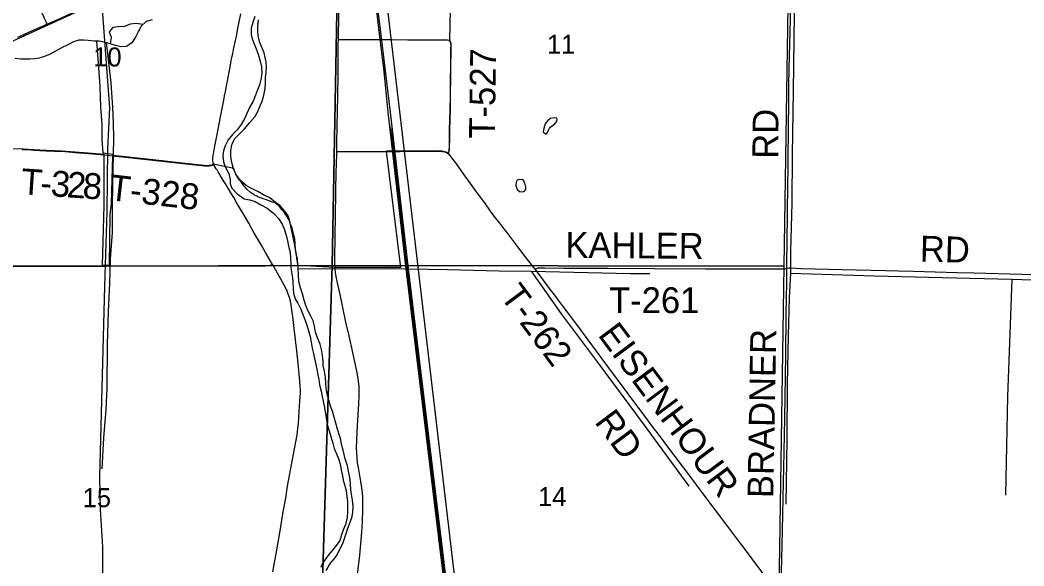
# Model space of a CAD drawing. Extents: x -8.3 to 42.1, y 0 to 22.
# Drawn here: x 5.164 to 7.372, y 15.682 to 16.882 of the extents above; entities that cross this region are included whole.
import ezdxf

# ---------------------------------------------------------------- set-up
doc = ezdxf.new("R2010")
doc.units = 0
for name, color, linetype in [('GM_X_City_Street', 7, 'Continuous'), ('GM_X_Corporation', 7, 'Continuous'), ('GM_X_County_Road', 7, 'Continuous'), ('GM_X_Major_River', 7, 'Continuous'), ('GM_X_Minor_Lake', 7, 'Continuous'), ('GM_X_Minor_River', 7, 'Continuous'), ('GM_X_Rail_Line', 7, 'Continuous'), ('GM_X_Section', 7, 'Continuous'), ('GM_X_Section_Text', 7, 'Continuous'), ('GM_X_State_Route', 7, 'Continuous'), ('GM_X_Township_Road', 7, 'Continuous'), ('GM_X_Township_Road_Text', 7, 'Continuous')]:
    doc.layers.add(name, color=color, linetype=linetype)

msp = doc.modelspace()

# ---------------------------------------------------------------- linework, layer by layer
at = {"layer": 'GM_X_City_Street'}
for points in [[(5.2228, 16.873), (5.2206, 16.8781), (5.2187, 16.8825), (5.2174, 16.8853), (5.2155, 16.8895), (5.2128, 16.8951), (5.2102, 16.9009)], [(5.8638, 16.8392), (5.8673, 16.8392), (5.8799, 16.8392), (5.8923, 16.839), (5.9124, 16.8392), (5.9202, 16.8391), (5.9341, 16.8391), (5.945, 16.8391), (5.9574, 16.839), (5.9822, 16.8388), (6.0163, 16.8387), (6.0349, 16.8387), (6.0535, 16.8386), (6.0815, 16.8386), (6.097, 16.8385), (6.1017, 16.8382), (6.1041, 16.8381), (6.1066, 16.8376), (6.1084, 16.8364)]]:
    msp.add_lwpolyline(points, dxfattribs=at)
at = {"layer": 'GM_X_Corporation'}
msp.add_lwpolyline([(6.1166, 17.2491), (6.1082, 16.8369), (6.1097, 16.8351), (6.1107, 16.8333), (6.1112, 16.8306), (6.1113, 16.8268), (6.111, 16.8225), (6.1109, 16.8163), (6.1108, 16.8102), (6.1109, 16.8024), (6.1106, 16.79), (6.1107, 16.7806), (6.1106, 16.776), (6.1106, 16.7698), (6.1106, 16.7667), (6.1105, 16.7652), (6.1103, 16.759), (6.11, 16.7497), (6.1101, 16.7451), (6.11, 16.7435), (6.1098, 16.7311), (6.1098, 16.7156), (6.1094, 16.6845), (6.1083, 16.6411), (6.1079, 16.6209), (6.1075, 16.6023), (6.1073, 16.5967), (6.1069, 16.5939), (6.1055, 16.5883), (6.1031, 16.5901), (6.1006, 16.5914), (6.0973, 16.5925), (6.0918, 16.5933), (6.084, 16.5938), (6.07, 16.5941), (6.0263, 16.5939), (5.9997, 16.5937), (5.9841, 16.5936), (5.9691, 16.5936), (6.0001, 16.3379), (5.856, 16.3381), (5.7751, 16.3419), (5.7739, 16.3491), (5.7736, 16.3535), (5.7736, 16.3573), (5.7729, 16.3598), (5.7724, 16.3626), (5.7712, 16.3671), (5.7701, 16.3728), (5.7701, 16.3749), (5.7692, 16.3778), (5.7679, 16.4016), (5.7675, 16.4046), (5.7653, 16.411), (5.7644, 16.4158), (5.7625, 16.4214), (5.7611, 16.4267), (5.7589, 16.4319), (5.7576, 16.4346), (5.7573, 16.4357), (5.7566, 16.4381), (5.7538, 16.4446), (5.7534, 16.4459), (5.752, 16.448), (5.7514, 16.4492), (5.7502, 16.4506), (5.7481, 16.4535), (5.7461, 16.4563), (5.7446, 16.4594), (5.7427, 16.462), (5.7394, 16.4649), (5.7378, 16.4667), (5.7371, 16.468), (5.734, 16.4722), (5.7315, 16.475), (5.7308, 16.4756), (5.7278, 16.4772), (5.7273, 16.4776), (5.7267, 16.4781), (5.7245, 16.4797), (5.7236, 16.4802), (5.7228, 16.4805), (5.7216, 16.481), (5.7191, 16.4817), (5.7166, 16.4823), (5.7114, 16.4842), (5.7093, 16.4851), (5.7032, 16.4873), (5.6986, 16.4887), (5.6944, 16.4906), (5.6899, 16.4918), (5.6864, 16.493), (5.6846, 16.4943), (5.6794, 16.4971), (5.6777, 16.4985), (5.6757, 16.4995), (5.6725, 16.5013), (5.6704, 16.5028), (5.6628, 16.509), (5.6542, 16.5193), (5.6514, 16.5237), (5.6491, 16.5273), (5.6485, 16.5278), (5.6476, 16.5286), (5.6465, 16.53), (5.6443, 16.5324), (5.6425, 16.5345), (5.641, 16.5369), (5.6406, 16.5378), (5.6398, 16.5397), (5.6385, 16.5425), (5.6374, 16.545), (5.6372, 16.5457), (5.637, 16.5464), (5.6365, 16.5477), (5.6355, 16.5494), (5.6352, 16.55), (5.6347, 16.5527), (5.6343, 16.5537), (5.634, 16.5544), (5.634, 16.5548), (5.6338, 16.5555), (5.5894, 16.565), (5.5867, 16.5636), (5.5836, 16.5624), (5.5795, 16.5618), (5.5764, 16.5615), (5.5733, 16.5616), (5.5687, 16.5619), (5.5146, 16.568), (5.4621, 16.5739), (5.4019, 16.5803), (5.367, 16.5841), (5.3636, 16.4788), (5.3613, 16.4541), (5.3595, 16.342), (5.3451, 16.3421), (5.3486, 16.4746), (5.3482, 16.4891), (5.3489, 16.586), (5.3401, 16.5869), (5.3137, 16.589), (5.2843, 16.5916), (5.2549, 16.5939), (5.2394, 16.5945), (5.2208, 16.595), (5.2068, 16.5956), (5.1929, 16.5966), (5.1805, 16.5976), (5.1711, 16.5978), (5.168, 16.5978), (5.1062, 16.5996)], dxfattribs=at)
at = {"layer": 'GM_X_County_Road'}
for points in [[(5.5896, 16.5645), (5.5884, 16.5683), (5.5876, 16.5725), (5.5874, 16.5758), (5.5874, 16.5788), (5.588, 16.5834), (5.5897, 16.5925), (5.592, 16.6047), (5.5957, 16.623), (5.6001, 16.6459), (5.6038, 16.6657), (5.6109, 16.7022), (5.6143, 16.7189), (5.6159, 16.7281), (5.6171, 16.7341), (5.6182, 16.7402), (5.6191, 16.7447), (5.6197, 16.7478), (5.6212, 16.7553), (5.6236, 16.7674), (5.6249, 16.775), (5.6263, 16.7825), (5.6282, 16.7931), (5.6294, 16.7992), (5.6313, 16.8083), (5.6331, 16.8174), (5.6375, 16.8371), (5.6394, 16.8461), (5.642, 16.8596), (5.6434, 16.8671), (5.6449, 16.8745), (5.6492, 16.8958)], [(5.8638, 16.8392), (5.8649, 16.8943), (5.8651, 16.9135)], [(5.8602, 16.593), (5.8606, 16.613), (5.8613, 16.6456), (5.862, 16.6829), (5.8625, 16.714), (5.8629, 16.7653), (5.8632, 16.7886), (5.8636, 16.8073), (5.8636, 16.8321), (5.8638, 16.8392)], [(5.8563, 16.3375), (5.8562, 16.3432), (5.856, 16.3534), (5.8566, 16.4109), (5.8572, 16.4482), (5.8581, 16.5057), (5.8591, 16.5492), (5.8594, 16.5632), (5.8602, 16.5897), (5.8602, 16.593)], [(5.7186, 16.3446), (5.7036, 16.3705), (5.695, 16.3853), (5.678, 16.4149), (5.6734, 16.423), (5.6665, 16.4351), (5.654, 16.4565), (5.6405, 16.4793), (5.6336, 16.4914), (5.6273, 16.5021), (5.6169, 16.5194), (5.6111, 16.5286), (5.6047, 16.5392), (5.6016, 16.5445), (5.5993, 16.5485), (5.5968, 16.5524), (5.5951, 16.555), (5.5928, 16.5585), (5.5908, 16.5618), (5.5896, 16.5645)], [(5.7198, 15.6684), (5.7276, 15.7128), (5.7305, 15.7297), (5.7347, 15.7542), (5.7425, 15.8002), (5.7478, 15.8308), (5.7521, 15.8569), (5.7585, 15.8921), (5.7653, 15.9272), (5.7705, 15.9547), (5.7731, 15.97), (5.7749, 15.9839), (5.776, 15.9948), (5.7777, 16.0212), (5.7791, 16.0444), (5.7801, 16.0615), (5.7802, 16.0694), (5.78, 16.0772), (5.7791, 16.0881), (5.7751, 16.1267), (5.7721, 16.1546), (5.7663, 16.204), (5.7634, 16.2302), (5.7617, 16.2441), (5.7598, 16.2565), (5.7583, 16.2641), (5.7562, 16.2717), (5.7535, 16.2791), (5.75, 16.2877), (5.7453, 16.2976), (5.7402, 16.3073), (5.7192, 16.3436), (5.7186, 16.3446)], [(5.9051, 15.6572), (5.9106, 15.705), (5.9141, 15.739), (5.9154, 15.756), (5.9167, 15.7792), (5.9176, 15.8056), (5.9177, 15.8196), (5.9175, 15.832), (5.9168, 15.8428), (5.9156, 15.8535), (5.9133, 15.8673), (5.9085, 15.8933), (5.9061, 15.9086), (5.9048, 15.9195), (5.9041, 15.9304), (5.9039, 15.9413), (5.9041, 15.9568), (5.905, 15.977), (5.9074, 16.0143), (5.9086, 16.0375), (5.9093, 16.0561), (5.9094, 16.0685), (5.9091, 16.0778), (5.9083, 16.0855), (5.907, 16.0946), (5.9042, 16.1099), (5.9007, 16.1266), (5.8953, 16.1509), (5.8871, 16.1872), (5.8803, 16.2176), (5.8735, 16.2495), (5.8673, 16.2783), (5.8618, 16.3041), (5.8589, 16.3178), (5.8573, 16.3271), (5.8564, 16.3348), (5.8563, 16.3375)]]:
    msp.add_lwpolyline(points, dxfattribs=at)
at = {"layer": 'GM_X_Major_River'}
for points in [[(5.4539, 16.8824), (5.4409, 16.8786), (5.4297, 16.8686), (5.4233, 16.8559), (5.4177, 16.8442), (5.4095, 16.8315), (5.3975, 16.8235), (5.3854, 16.823), (5.3734, 16.8263), (5.3621, 16.8296), (5.3489, 16.8334), (5.3372, 16.8352), (5.327, 16.8358), (5.313, 16.8373), (5.3028, 16.8379), (5.293, 16.8378), (5.2811, 16.8339), (5.2685, 16.8277), (5.2562, 16.8216), (5.2428, 16.8139), (5.2297, 16.8066), (5.2175, 16.802), (5.2053, 16.7978), (5.1958, 16.7965), (5.1852, 16.796), (5.1753, 16.7962), (5.1655, 16.7961), (5.1526, 16.7975)], [(5.6798, 16.8899), (5.6753, 16.8767), (5.6716, 16.8639), (5.672, 16.8498), (5.674, 16.8403), (5.6783, 16.8299), (5.6829, 16.8184), (5.6876, 16.8066), (5.6917, 16.7913), (5.6945, 16.7787), (5.6953, 16.7665), (5.6942, 16.754), (5.6904, 16.7393), (5.686, 16.7284), (5.6815, 16.7171), (5.6763, 16.7032), (5.6684, 16.6894), (5.6624, 16.6762), (5.658, 16.6661), (5.6501, 16.6526), (5.6414, 16.6407), (5.6306, 16.63), (5.6216, 16.6184), (5.6144, 16.6053), (5.6107, 16.594), (5.6093, 16.5838), (5.6113, 16.5705), (5.6151, 16.5575), (5.6224, 16.5444), (5.6258, 16.5314), (5.626, 16.5219), (5.6295, 16.5123), (5.641, 16.4999), (5.6562, 16.4885), (5.6686, 16.4863), (5.6807, 16.4826), (5.6934, 16.4759), (5.7068, 16.4679), (5.7209, 16.457), (5.732, 16.4453), (5.7404, 16.433)], [(5.8086, 16.2207), (5.8032, 16.2311), (5.796, 16.2445), (5.7913, 16.2564), (5.7882, 16.266), (5.7851, 16.2801), (5.7805, 16.2931), (5.7771, 16.3068), (5.7759, 16.3209), (5.7751, 16.3354), (5.7743, 16.3483), (5.7726, 16.3578), (5.7714, 16.3673), (5.7697, 16.3776), (5.7674, 16.3906), (5.7643, 16.4043), (5.7623, 16.4146), (5.7592, 16.4276), (5.7572, 16.4394), (5.7535, 16.4511), (5.746, 16.4617), (5.7354, 16.4737), (5.722, 16.4837), (5.7131, 16.4913), (5.6992, 16.4977), (5.6862, 16.5049), (5.6738, 16.5105), (5.6607, 16.518), (5.6489, 16.5282), (5.6382, 16.5432), (5.6332, 16.5551), (5.629, 16.5685), (5.6271, 16.5815), (5.6274, 16.5944), (5.6292, 16.6072), (5.6349, 16.6204), (5.6446, 16.6304), (5.6574, 16.6426), (5.6687, 16.6564), (5.6796, 16.669), (5.6859, 16.6791), (5.6912, 16.6919), (5.696, 16.7035), (5.7001, 16.7171), (5.7028, 16.7313), (5.7034, 16.7424), (5.7037, 16.7557), (5.7051, 16.7655), (5.7058, 16.7799), (5.705, 16.7898), (5.7029, 16.7997), (5.7005, 16.81), (5.6944, 16.8235), (5.6905, 16.8338), (5.6875, 16.8479), (5.6866, 16.8574), (5.6865, 16.8688), (5.6879, 16.8825)], [(5.7404, 16.433), (5.7447, 16.4226), (5.7489, 16.4089), (5.752, 16.3963), (5.7551, 16.3818), (5.7574, 16.3715), (5.7586, 16.3574), (5.7588, 16.3479), (5.7593, 16.3376), (5.7605, 16.3281), (5.7629, 16.3152), (5.7638, 16.3053), (5.7642, 16.2927), (5.765, 16.281), (5.7689, 16.2687), (5.7744, 16.2591), (5.7812, 16.246), (5.7848, 16.2364), (5.7898, 16.2234), (5.7944, 16.2112), (5.7982, 16.1982), (5.8013, 16.186), (5.8037, 16.1738), (5.8064, 16.1604), (5.8087, 16.1486), (5.8111, 16.1375), (5.8142, 16.1242), (5.8169, 16.1108), (5.8185, 16.1013), (5.8206, 16.0914), (5.8222, 16.0799), (5.8256, 16.0662), (5.8283, 16.054), (5.83, 16.0437), (5.8334, 16.0299), (5.8354, 16.0162), (5.84, 15.9907)], [(5.837, 15.6716), (5.8462, 15.6877), (5.856, 15.6983), (5.861, 15.7059), (5.8666, 15.7187), (5.8734, 15.7311), (5.8778, 15.7442), (5.8815, 15.7548), (5.8848, 15.7646), (5.89, 15.7777), (5.8938, 15.7902), (5.8955, 15.8), (5.8962, 15.8121), (5.895, 15.8265), (5.8927, 15.8391), (5.891, 15.849), (5.8906, 15.8612), (5.8897, 15.8722), (5.887, 15.886), (5.8837, 15.902), (5.8783, 15.9169), (5.8767, 15.9264), (5.8743, 15.9364), (5.8708, 15.9493), (5.8688, 15.9589), (5.8664, 15.9684), (5.8618, 15.9822), (5.8581, 15.9957), (5.8545, 16.0089), (5.851, 16.0219), (5.8464, 16.0331), (5.8429, 16.0464), (5.8391, 16.0594), (5.8367, 16.0723), (5.8359, 16.083), (5.8351, 16.0967), (5.8335, 16.1096), (5.8304, 16.1226), (5.8303, 16.1321), (5.8291, 16.1443), (5.8267, 16.1573), (5.8234, 16.1693), (5.8175, 16.1829), (5.8133, 16.1959), (5.8113, 16.2085), (5.8086, 16.2207)], [(5.84, 15.9907), (5.8431, 15.9785), (5.847, 15.9659), (5.8516, 15.9513), (5.8547, 15.9399), (5.8597, 15.9284), (5.865, 15.9153), (5.8685, 15.9027), (5.8702, 15.8921), (5.8725, 15.8799), (5.8745, 15.8703), (5.8783, 15.8558), (5.8807, 15.8459), (5.8824, 15.8352), (5.8839, 15.8223), (5.8841, 15.8124), (5.8841, 15.7995), (5.8831, 15.7878), (5.8793, 15.773), (5.8749, 15.7625), (5.8708, 15.7497), (5.8667, 15.7373), (5.8573, 15.7242), (5.8456, 15.7105), (5.8381, 15.7008), (5.8295, 15.6885), (5.8251, 15.6783)]]:
    msp.add_lwpolyline(points, dxfattribs=at)
at = {"layer": 'GM_X_Minor_Lake'}
for p, q in [((6.3289, 16.646), (6.332, 16.6479)), ((6.2753, 16.5172), (6.2736, 16.5229))]:
    msp.add_line(p, q, dxfattribs=at)
for points in [[(6.332, 16.6479), (6.3393, 16.653), (6.3436, 16.6578), (6.3452, 16.6635), (6.3442, 16.6662), (6.3396, 16.6667), (6.3305, 16.6654), (6.3247, 16.6609), (6.3189, 16.6539), (6.3156, 16.6437), (6.3142, 16.6358), (6.3191, 16.6319), (6.3217, 16.6318), (6.3245, 16.6363), (6.3269, 16.6412), (6.3289, 16.646)], [(6.2736, 16.5229), (6.2722, 16.5271), (6.27, 16.5302), (6.2632, 16.5311), (6.2567, 16.5301), (6.2547, 16.5256), (6.2538, 16.5184), (6.2573, 16.5093), (6.2621, 16.505), (6.2686, 16.5044), (6.2731, 16.5058), (6.2759, 16.5096), (6.2764, 16.5149), (6.2753, 16.5172)]]:
    msp.add_lwpolyline(points, dxfattribs=at)
at = {"layer": 'GM_X_Minor_River'}
for points in [[(6.7333, 17.2723), (6.7481, 17.1645), (6.7559, 17.1283), (6.7642, 17.0958), (6.7715, 17.0862), (6.779, 17.0818), (6.8507, 17.0725), (6.8666, 17.0717), (6.8667, 16.9529), (6.8644, 16.7253), (6.8617, 16.5857), (6.861, 16.4802), (6.8584, 16.374), (6.8579, 16.325), (6.8551, 16.2708), (6.853, 16.1878), (6.8511, 16.0815), (6.8504, 15.9601), (6.848, 15.8175)], [(5.434, 16.8724), (5.4189, 16.8746), (5.4056, 16.8726), (5.3929, 16.8676), (5.3797, 16.8672), (5.3679, 16.8659), (5.3597, 16.8559), (5.364, 16.844), (5.3621, 16.8296)], [(5.332, 16.8355), (5.3358, 16.7779), (5.3389, 16.7357), (5.3408, 16.6901), (5.3437, 16.6525), (5.3436, 16.6183), (5.3455, 16.5902), (5.3682, 16.5869)], [(5.3527, 16.8323), (5.358, 16.7884), (5.3634, 16.7438), (5.367, 16.6898), (5.368, 16.6553), (5.3693, 16.6225), (5.3682, 16.5869), (5.3678, 16.5528), (5.3671, 16.5186), (5.3661, 16.4724), (5.3662, 16.4147), (5.3614, 16.3571), (5.3604, 16.3033), (5.357, 16.2411), (5.3548, 16.1687), (5.3547, 16.0727), (5.3524, 16.0253), (5.3474, 15.9635), (5.3431, 15.8949)], [(5.7751, 16.3354), (5.8656, 16.3347), (5.9758, 16.3354), (6.1041, 16.3335), (6.2177, 16.3307), (6.2877, 16.3294), (6.4134, 16.3267), (6.5057, 16.3248), (6.5489, 16.3249)], [(6.2877, 16.3294), (6.3539, 16.2359), (6.4327, 16.1304), (6.5361, 15.9909), (6.6346, 15.8568)], [(6.8579, 16.325), (7.0433, 16.3198), (7.1925, 16.3161), (7.3453, 16.312), (7.477, 16.3081), (7.5894, 16.305), (7.737, 16.3018), (7.8449, 16.2992), (7.8434, 16.1334), (7.8408, 16.0427), (7.8376, 15.9449), (7.8354, 15.8379), (7.833, 15.7279), (7.8304, 15.6084)], [(7.3453, 16.312), (7.34, 16.1729), (7.3359, 16.0542), (7.3309, 15.8372)]]:
    msp.add_lwpolyline(points, dxfattribs=at)
at = {"layer": 'GM_X_Rail_Line'}
for q in [(5.9763, 16.655), (5.9819, 16.6458)]:
    msp.add_line((5.9835, 16.6131), q, dxfattribs=at)
for points in [[(5.9654, 16.7643), (5.9567, 16.8335), (5.932, 17.0379), (5.9087, 17.2246), (5.8981, 17.3081), (5.8822, 17.4435), (5.8389, 17.6857), (5.7322, 18.3104), (5.5565, 19.3262), (5.427, 20.0822), (5.2858, 20.9)], [(6.2899, 14.1), (6.2222, 14.6512), (6.0176, 16.3351), (5.9781, 16.679), (5.9602, 16.8313), (5.9345, 17.0381), (5.9111, 17.2249), (5.9006, 17.3084), (5.8846, 17.4439), (5.8413, 17.6862), (5.7347, 18.3108), (5.559, 19.3267), (5.4294, 20.0826), (5.2883, 20.9)], [(5.9383, 17.037), (5.9498, 17.0314), (5.958, 17.0231), (6.2364, 14.6613)], [(3.5481, 16.7901), (3.5751, 16.7924), (3.642, 16.7979), (3.7302, 16.7871), (4.0849, 16.6622), (4.2594, 16.6204), (4.3265, 16.61), (4.5771, 16.6383), (4.6964, 16.6517), (4.847, 16.6995), (5.3428, 16.9248)], [(5.3428, 16.9248), (5.3604, 16.689), (5.3556, 16.5985), (5.3541, 16.4612), (5.3493, 16.2965), (5.3382, 15.8766), (5.3398, 15.8056), (5.3447, 15.7232), (5.3447, 15.6312), (5.3415, 15.5213), (5.3256, 14.9739), (5.302, 14.1)], [(6.178, 14.9941), (6.1617, 15.1075), (6.0126, 16.3345), (5.9736, 16.679), (5.9639, 16.7758)], [(6.1529, 15.1995), (6.1528, 15.2014), (6.0151, 16.3348), (5.9835, 16.6131)]]:
    msp.add_lwpolyline(points, dxfattribs=at)
at = {"layer": 'GM_X_Section'}
for points in [[(5.8682, 17.3386), (5.8503, 16.3424), (4.8464, 16.3395), (4.866, 17.3546), (5.431, 17.3522)], [(6.8593, 17.3438), (6.8436, 16.3404), (5.8503, 16.3424), (5.8682, 17.3386)], [(4.8464, 16.3395), (5.8503, 16.3424), (5.8197, 15.3608), (4.8204, 15.3344)], [(5.8503, 16.3424), (6.8436, 16.3404), (6.8279, 15.3401), (5.8197, 15.3608)]]:
    msp.add_lwpolyline(points, close=True, dxfattribs=at)
at = {"layer": 'GM_X_State_Route'}
msp.add_lwpolyline([(5.1589, 16.8442), (5.1715, 16.8501), (5.1828, 16.8552), (5.2025, 16.8642), (5.2209, 16.8722), (5.2228, 16.873), (5.2326, 16.8773), (5.2531, 16.8864), (5.2686, 16.8933), (5.2769, 16.8974), (5.284, 16.9005), (5.2872, 16.902), (5.2956, 16.9059), (5.3006, 16.908), (5.3091, 16.9116), (5.3176, 16.9154), (5.3316, 16.9218), (5.3356, 16.9237), (5.3499, 16.9301), (5.3519, 16.931)], dxfattribs=at)
at = {"layer": 'GM_X_Township_Road'}
for points in [[(6.8503, 16.3361), (6.8505, 16.3485), (6.8511, 16.3936), (6.8526, 16.521), (6.853, 16.5537), (6.8534, 16.5987), (6.8535, 16.6189), (6.8539, 16.6562), (6.8543, 16.6904), (6.8549, 16.7371), (6.8555, 16.7759), (6.8581, 16.8831), (6.859, 16.9266), (6.8596, 16.9608), (6.8606, 16.9904), (6.8618, 17.0152), (6.8629, 17.0416), (6.8638, 17.0649), (6.865, 17.0928), (6.8655, 17.1115), (6.8673, 17.1829), (6.868, 17.2093), (6.8681, 17.2212)], [(6.1058, 16.5878), (6.1071, 16.5933), (6.1075, 16.5962), (6.1078, 16.6017), (6.1081, 16.6203), (6.1085, 16.6405), (6.1096, 16.684), (6.11, 16.7151), (6.11, 16.7306), (6.1102, 16.743), (6.1103, 16.7445), (6.1103, 16.7492), (6.1105, 16.7585), (6.1107, 16.7646), (6.1108, 16.7662), (6.1109, 16.7693), (6.1108, 16.7754), (6.1109, 16.7801), (6.1108, 16.7894), (6.1111, 16.8018), (6.111, 16.8096), (6.1111, 16.8157), (6.1113, 16.8219), (6.1115, 16.8262), (6.1114, 16.8301), (6.1109, 16.8328), (6.1099, 16.8345), (6.1084, 16.8364)], [(5.1683, 16.5972), (5.1714, 16.5973), (5.1807, 16.597), (5.1931, 16.5961), (5.207, 16.595), (5.221, 16.5944), (5.2344, 16.5941)], [(5.2344, 16.5941), (5.2396, 16.5939), (5.2551, 16.5933), (5.2846, 16.591), (5.314, 16.5884), (5.3403, 16.5863), (5.3491, 16.5855), (5.35, 16.5854)], [(5.35, 16.5854), (5.3573, 16.5846), (5.3672, 16.5835)], [(5.3672, 16.5835), (5.4021, 16.5798), (5.4623, 16.5733), (5.5148, 16.5675), (5.5689, 16.5613), (5.5735, 16.561), (5.5766, 16.561), (5.5797, 16.5613), (5.5838, 16.5619), (5.5869, 16.563), (5.5896, 16.5645)], [(5.8602, 16.593), (5.8644, 16.5931), (5.872, 16.5931), (5.8783, 16.5929), (5.9096, 16.593), (5.9486, 16.5932), (5.9693, 16.593)], [(5.9693, 16.593), (5.9843, 16.593), (5.9999, 16.5931), (6.0265, 16.5933), (6.0703, 16.5936), (6.0843, 16.5933), (6.092, 16.5927), (6.0976, 16.592), (6.1008, 16.5909), (6.1033, 16.5896), (6.1058, 16.5878)], [(6.1058, 16.5878), (6.1091, 16.5843), (6.1128, 16.5791), (6.1184, 16.5716), (6.121, 16.5678), (6.1329, 16.5514), (6.1419, 16.5387), (6.15, 16.5274), (6.1648, 16.5074), (6.1776, 16.4898), (6.1849, 16.4797), (6.1975, 16.462), (6.2059, 16.4509), (6.2184, 16.4351), (6.225, 16.4264), (6.2334, 16.4152), (6.2466, 16.398), (6.258, 16.3832), (6.2741, 16.3623), (6.2903, 16.3414), (6.2959, 16.3339)], [(4.8434, 16.3396), (4.866, 16.34), (4.8877, 16.3404), (4.9064, 16.3409), (4.9374, 16.3415), (4.9591, 16.3416), (5.012, 16.3415), (5.0773, 16.3412), (5.1239, 16.3411), (5.1643, 16.3411), (5.1891, 16.3412), (5.2575, 16.3414), (5.3443, 16.3415)], [(5.3443, 16.3415), (5.3453, 16.3415), (5.3597, 16.3414)], [(5.3597, 16.3414), (5.3645, 16.3414), (5.4111, 16.3413), (5.4453, 16.3414), (5.5136, 16.3415), (5.5758, 16.3415), (5.6068, 16.3414), (5.6503, 16.3413), (5.6938, 16.3413), (5.7032, 16.3415), (5.7081, 16.3419), (5.7126, 16.3429), (5.7186, 16.3446)], [(6.2959, 16.3339), (6.2995, 16.3358), (6.3032, 16.3367), (6.3063, 16.3369), (6.3172, 16.3369), (6.3592, 16.3366), (6.4058, 16.3362), (6.4571, 16.3361), (6.5581, 16.3354), (6.6716, 16.3349), (6.7679, 16.3347), (6.8208, 16.3346), (6.8348, 16.3348), (6.8425, 16.3347), (6.846, 16.3351), (6.8496, 16.336), (6.8503, 16.3361)], [(6.2959, 16.3339), (6.3052, 16.3215), (6.3276, 16.2917), (6.3388, 16.2768), (6.3575, 16.252), (6.3669, 16.2396), (6.394, 16.2036), (6.4079, 16.1849), (6.4558, 16.1198), (6.5219, 16.0315), (6.5312, 16.0191), (6.5534, 15.9891), (6.5693, 15.968), (6.59, 15.9408), (6.6338, 15.8824), (6.6654, 15.8401), (6.7131, 15.7768), (6.7393, 15.7421), (6.7626, 15.711), (6.7812, 15.6861), (6.8037, 15.6564)], [(6.8368, 15.6155), (6.8368, 15.6166), (6.8376, 15.6415), (6.8388, 15.6974), (6.8404, 15.7595), (6.8425, 15.8668), (6.8433, 15.8963), (6.8455, 16.0066), (6.8478, 16.1449), (6.8489, 16.232), (6.8496, 16.2739), (6.85, 16.3019), (6.8503, 16.3361)], [(6.8503, 16.3361), (6.8538, 16.3367), (6.8579, 16.3368), (6.8812, 16.3359), (6.9123, 16.3348), (6.9713, 16.3335), (7.0676, 16.331), (7.0956, 16.3303), (7.1282, 16.3296), (7.2246, 16.3271), (7.2618, 16.3259), (7.3675, 16.3231), (7.439, 16.3209), (7.5042, 16.3193), (7.5757, 16.3171), (7.6083, 16.3162), (7.6487, 16.3151), (7.7792, 16.3111), (7.846, 16.3088), (7.8522, 16.3089), (7.8589, 16.309)]]:
    msp.add_lwpolyline(points, dxfattribs=at)

# ---------------------------------------------------------------- texts
at = {"layer": 'GM_X_Section_Text'}
for s, p in [('11', (6.3225, 16.8077)), ('10', (5.3246, 16.7798)), ('14', (6.303, 15.813)), ('15', (5.3013, 15.8107))]:
    msp.add_text(s, height=0.04186, rotation=0, dxfattribs=at).set_placement(p)
at = {"layer": 'GM_X_Township_Road_Text'}
for s, height, rotation, p in [('T-527', 0.05682, 89.1569, (6.2078, 16.6209)), ('RD', 0.05682, 89.5097, (6.8312, 16.5767)), ('T', 0.0568, 356.0799, (5.1642, 16.4992)), ('3', 0.0568, 356.0863, (5.2299, 16.4947)), ('2', 0.0568, 356.1312, (5.2649, 16.4923)), ('8', 0.0568, 356.3202, (5.3, 16.4899)), ('T-328', 0.05682, 353.5679, (5.3571, 16.4863)), ('-', 0.0568, 356.0629, (5.2066, 16.4963)), ('KAHLER', 0.05682, 359.4938, (6.363, 16.3593)), ('RD', 0.05682, 358.5193, (7.1423, 16.351)), ('T-262', 0.05682, 306.76, (6.2176, 16.2746)), ('T-261', 0.05682, 0, (6.4592, 16.2374)), ('EISENHOUR', 0.05682, 306.7256, (6.433, 16.1893)), ('BRADNER', 0.05682, 88.9919, (6.8204, 15.8305)), ('RD', 0.05682, 306.6892, (6.4257, 15.998))]:
    msp.add_text(s, height=height, rotation=rotation, dxfattribs=at).set_placement(p)

doc.saveas('drawing.dxf')
